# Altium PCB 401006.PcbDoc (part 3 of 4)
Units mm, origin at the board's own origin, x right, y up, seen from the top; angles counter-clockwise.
Board outline 117 x 63.5 mm, 4 copper layers (Top Layer, Mid-Layer 1, Mid-Layer 2, Bottom Layer), stack 1.68 mm thick; 205 components, 151 nets, 838 pads, 1570 vias.
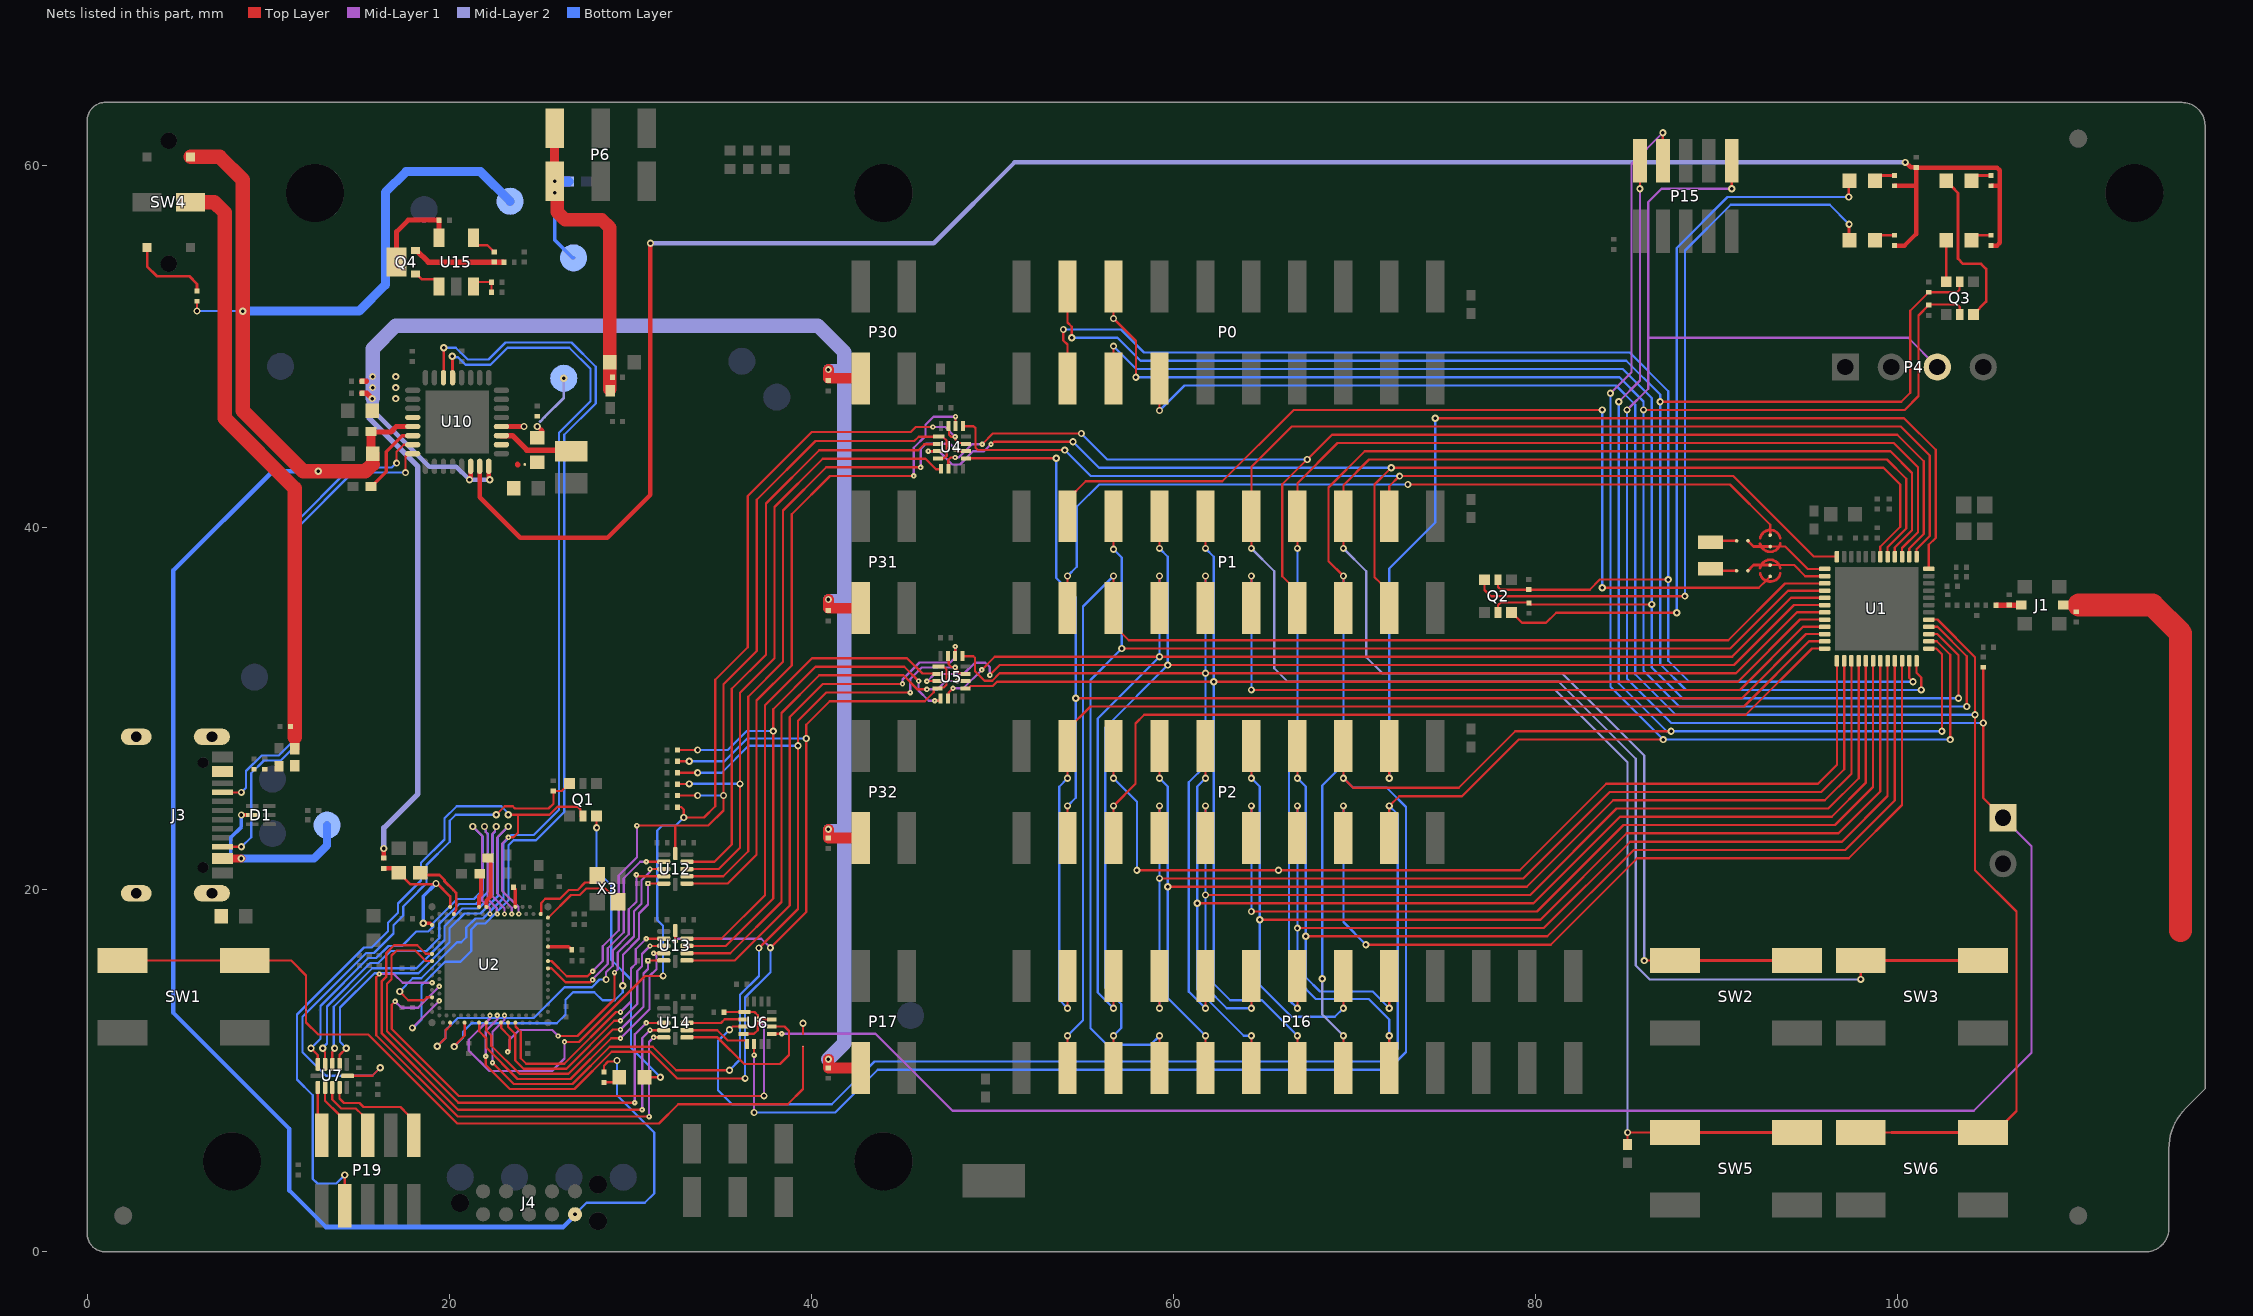
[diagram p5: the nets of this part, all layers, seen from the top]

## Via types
v1: diameter 0.4, hole 0.2, Top Layer to Bottom Layer, tented both sides, 1458 vias
v2: diameter 0.3, hole 0.1, Top Layer to Mid-Layer 1, tented top, 71 vias
v3: diameter 0.5, hole 0.25, Top Layer to Bottom Layer, tented both sides, 24 vias
v4: diameter 0.3, hole 0.1, Top Layer to Mid-Layer 1, tented both sides, 17 vias

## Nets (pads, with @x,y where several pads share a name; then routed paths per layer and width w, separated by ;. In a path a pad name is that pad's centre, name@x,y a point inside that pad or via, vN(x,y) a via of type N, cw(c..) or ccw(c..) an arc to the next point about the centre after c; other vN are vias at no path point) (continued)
NetC39_2: C39.2 U2.A15 | length 2.8
  Top Layer w0.225: U2.A15@22.06,19.064 22.06,19.42 22.286,19.646 22.286,21.619 C39.2@22.151,21.754
NetC42_1: C42.1 R40.1 U2.A5 U2.E1 | length 7.9
  Top Layer w0.15: C42.1@17,21.184 C42.1@17.231,20.952 ; C42.1@17.226,20.947 17.866,20.306 19.231,20.306 v1(19.275,20.35) 19.347,20.35 20.06,19.637 U2.A5@20.06,19.064
  Top Layer w0.2: v1@18.577,18.152 18.966,18.152 19.054,18.064 U2.E1@19.06,18.064
  Top Layer w0.25: R40.1@16.394,21.184 C42.1@17,21.184
  Bottom Layer w0.2: v1(18.575,18.15) 18.575,19.65 v1(19.275,20.35)
NetC43_1: C43.1 U2.B6 | length 3.7
  Top Layer w0.15: C43.1@18.527,20.825 19.472,20.825 19.75,20.547 19.75,20.475 20.235,19.99 20.391,19.834 20.391,18.938 ; U2.B6@20.26,18.664 20.391,18.934
  Top Layer w0.187: C43.1@18.4,20.952 C43.1@18.552,20.8
NetC44_1: C44.1 U2.A23 | length 1.1
  Top Layer w0.2: C44.1@23.55,20.154 23.55,20.139 23.66,20.029 U2.A23@23.66,19.064
NetC45_2: C45.2 U2.A13 | length 1.9
  Top Layer w0.225: U2.A13@21.66,19.064 21.66,19.644 21.77,19.754 C45.2@21.77,20.891
NetC59_1: C59.1 J3.SHLD
NetC64_2: C64.2 R2.2 R3.2 R19.2 R20.2 U10.31 | length 114.9
  Top Layer w0.25: U10.31@21.692,43.396 21.692,41.686 23.928,39.45 28.749,39.45 31.125,41.826 v1(31.125,55.727) ; R3.2@99.848,55.594 100.403,55.594 101.039,56.23 101.039,58.896 ; R19.2@99.848,58.896 101.039,58.896 ; v1(100.445,60.185) 100.468,60.185 100.743,59.91 101.029,59.91 C64.2@101.039,59.9 ; R2.2@105.182,55.594 105.515,55.594 105.661,55.74 105.661,58.896 ; R20.2@105.182,58.896 105.661,58.896 ; 101.039,58.896 C64.2@101.039,59.9 ; C64.2@101.039,59.9 105.515,59.9 105.661,59.754 105.661,58.896
  Mid-Layer 2 w0.25: v1(31.125,55.727) 46.777,55.727 51.235,60.185 v1(100.445,60.185)
NetC72_1: C72.1 R43.2 U15.3 | length 1.7
  Top Layer w0.125: U15.3@21.35,53.325 21.35,53.337 21.587,53.575 C72.1@22.35,53.575 R43.2@22.35,53.025
NetJ3_A5: J3.A5 U10.23 | length 26.4
  Top Layer w0.125: J3.A5@7.485,25.384 v1(8.526,25.384) ; v1(17.1,43.575) 17.097,43.578 17.097,44.197 17.493,44.593 17.988,44.593 U10.23@17.992,44.596
  Bottom Layer w0.125: v1(8.526,25.384) 8.785,25.643 8.785,26.565 9.648,27.428 10.586,27.428 11.275,28.116 11.275,40.046 14.556,43.327 16.839,43.327 17.087,43.575 v1(17.1,43.575)
NetJ3_B5: J3.B5 U10.24 | length 29.1
  Top Layer w0.125: v1(17.594,43.05) 17.591,43.053 17.591,43.935 17.752,44.096 U10.24@17.992,44.096
  Top Layer w0.15: J3.B5@7.485,22.384 v1(8.529,22.384)
  Bottom Layer w0.125: v1(8.529,22.384) 8.538,22.384 9.065,22.911 9.065,26.44 9.775,27.15 10.701,27.15 11.553,28.001 11.553,39.931 14.671,43.05 v1(17.594,43.05)
NetL8_2: L8.2 U10.3 | length 4.2
  Top Layer w0.3: U10.3@22.892,45.096 23.492,45.096 24.292,44.296 L8.2@26.749,44.296
NetLD1_1: LD1.1 Q1.6 | length 16.8
  Top Layer w0.125: v1(28.15,23.425) Q1.6@28.15,24.082 ; LD1.1@30.802,9.652 v1(31.674,9.652)
  Bottom Layer w0.125: v1(28.15,23.425) 28.15,21.075 28.966,20.259 28.966,16.14 30.055,15.051 30.055,11.272 v1(31.674,9.652)
NetLD1_2: LD1.2 R5.1 | length 1.4
  Top Layer w0.125: LD1.2@29.12,9.937 LD1.2@29.405,9.652
  Top Layer w0.15: R5.1@28.56,9.367 29.12,9.367 LD1.2@29.405,9.652
NetLD2_1: LD2.1 Q2.6 | length 41.3
  Top Layer w0.125: Q2.6@78.7,35.331 79.278,34.754 80.601,34.754 81.16,35.312 v1(87.814,35.312)
  Top Layer w0.15: v1(97.316,58.277) 97.316,59.125 LD2.1@97.371,59.181
  Bottom Layer w0.125: v1(87.814,35.312) 87.814,55.463 90.629,58.278 v1(97.316,58.277)
NetLD2_2: LD2.2 R19.1 | length 1.2
  Top Layer w0.15: LD2.2@98.768,59.181 99.053,59.466 R19.1@99.848,59.466
NetLD3_1: LD3.1 Q3.6 | length 9.2
  Top Layer w0.15: LD3.1@102.705,59.155 103.011,58.849 103.358,58.502 103.358,54.87 103.645,54.583 104.636,54.583 104.915,54.304 104.915,52.502 Q3.6@104.205,51.793
NetLD3_2: LD3.2 R20.1 | length 1.2
  Top Layer w0.15: LD3.2@104.102,59.181 104.387,59.466 R20.1@105.182,59.466
NetLD4_1: LD4.1 Q2.3 | length 42.3
  Top Layer w0.125: Q2.3@77.2,37.131 77.2,36.563 77.536,36.227 v1(88.272,36.227)
  Top Layer w0.15: v1(97.341,56.777) 97.341,55.909 LD4.1@97.371,55.879
  Bottom Layer w0.125: v1(88.272,36.227) 88.272,55.322 90.8,57.85 96.268,57.85 v1(97.341,56.777)
NetLD4_2: LD4.2 R3.1 | length 0.8
  Top Layer w0.15: LD4.2@99.053,56.164 R3.1@99.848,56.164
NetLD5_1: LD5.1 Q3.3 | length 2.3
  Top Layer w0.15: Q3.3@102.705,53.593 LD5.1@102.705,55.879
NetLD5_2: LD5.2 R2.1 | length 0.8
  Top Layer w0.15: LD5.2@104.387,56.164 R2.1@105.182,56.164
NetQ1_3: Q1.3 R8.1 U7.12 | length 31.3
  Top Layer w0.125: U7.12@14.4,9.725 15.75,9.725 v1(16.2,10.175) ; v1(22.608,24.15) 23.071,24.612 23.517,24.612 23.641,24.488 25.491,24.488 25.766,24.763 R8.1@25.766,25.449 ; R8.1@25.76,25.455 26.223,25.455 26.477,25.71 Q1.3@26.651,25.71
  Bottom Layer w0.125: v1(16.2,10.175) 15.75,9.725 13.2,9.725 11.9,11.025 11.9,12.983 15.429,16.512 15.848,16.512 16.925,17.589 16.925,18.05 17.462,18.588 17.462,19.081 18.183,19.802 18.371,19.99 18.753,20.372 18.753,21.369 20.043,22.66 20.043,23.824 20.369,24.15 v1(22.608,24.15)
NetQ4_1: Q4.1 U15.1 | length 1.7
  Top Layer w0.15: Q4.1@18.15,54.025 18.2,54.025 18.5,53.725 19.225,53.725 19.45,53.5 U15.1@19.45,53.325
NetQ4_2: Q4.2 R9.1 R38.2 | length 5.1
  Top Layer w0.3: Q4.2@18.15,55.325 18.2,55.325 18.851,54.674 R9.1@23.006,54.674
NetR7_1: R7.1 U2.L31 | length 1.4
  Top Layer w0.187: U2.L31@25.46,16.864 26.597,16.864 26.719,16.743 26.734,16.743 26.775,16.702 R7.1@26.775,16.687
NetR21_2: R21.2 U4.5 U12.9 | length 37
  Top Layer w0.125: R21.2@32.61,25.842 v1@33.255,25.842 ; U12.9@33.14,21.15 34.903,21.15 36.075,22.321 36.075,30.889 37.978,32.792 37.978,41.147 40.646,43.815 46.322,43.815 46.903,43.233 47.13,43.233 47.16,43.262 U4.5@47.178,43.262
  Bottom Layer w0.125: v1(33.267,25.855) v1(36.075,25.855)
NetR22_2: R22.2 U5.5 U13.9 | length 33.4
  Top Layer w0.125: R22.2@32.61,27.726 v1(33.728,27.726) ; U13.9@33.14,16.9 35.284,16.9 37.903,19.519 37.903,29.982 40.246,32.325 45.147,32.325 v2(45.936,31.536) ; v2(46.825,30.45) 47.113,30.45 47.16,30.497 U5.5@47.16,30.561
  Mid-Layer 1 w0.125: v2(45.936,31.536) 45.936,31.014 46.5,30.45 v2(46.825,30.45)
  Bottom Layer w0.125: v1(33.728,27.726) 35.401,27.726 36.445,28.77 v1(37.903,28.77)
NetR36_1: R36.1 SW4.3 | length 4.6
  Top Layer w0.15: SW4.3@3.321,55.488 3.321,54.428 3.849,53.9 5.646,53.9 6.075,53.471 R36.1@6.075,53.085
NetR38_1: R38.1 U15.4 | length 1.6
  Top Layer w0.125: U15.4@21.35,56.025 21.35,55.825 21.572,55.603 22.126,55.603 R38.1@22.485,55.245
NetSB1_2: SB1.2 SB2.1 SW1.2 | length 45.9
  Top Layer w0.125: SW1.2@1.963,16.097 SW1.2@8.713,16.097 11.277,16.097 12.1,15.273 12.1,14.91 ; 12.1,14.864 SB2.1@12.1,13.364 12.1,12.675 12.766,12.009 15.541,12.009 20.457,7.093 31.594,7.093 32.661,8.16 38.716,8.16 39.55,8.994 SB1.2@39.55,11.35
NetSB3_2: SB3.2 X2.1 | length 1.5
  Top Layer w0.15: X2.1@89.689,39.192 89.777,39.28 SB3.2@91.129,39.28
NetSB4_2: SB4.2 X2.2 | length 1.5
  Top Layer w0.15: X2.2@89.689,37.742 89.802,37.629 SB4.2@91.129,37.629
NetU2_B30: U2.B30 X3.3 | length 4.3
  Top Layer w0.125: U2.B30@25.06,18.664 25.079,18.684 25.079,18.754 25.085,18.76 25.085,19.273 25.315,19.502 26.122,19.502 26.61,19.99 27.102,19.99 27.515,20.403 27.79,20.403 X3.3@28.181,20.794
NetU2_C31: U2.C31 X3.1 | length 4.9
  Top Layer w0.125: U2.C31@25.46,18.464 25.485,18.464 26.735,19.715 27.216,19.715 27.573,20.072 28.632,20.072 28.948,19.756 28.968,19.756 29.331,19.394 X3.1@29.331,19.344
NetU4_2: U4.2 U12.10 | length 33.4
  Top Layer w0.125: U12.10@33.14,21.55 34.657,21.55 35.617,22.511 35.617,31.103 37.503,32.989 37.503,41.344 40.45,44.29 45.926,44.29 46.255,44.619 46.984,44.619 U4.2@47.003,44.637
NetU4_10: U4.10 U12.8 | length 36
  Top Layer w0.125: U12.8@33.14,20.75 35.15,20.75 36.532,22.132 36.532,30.674 38.453,32.596 38.453,40.95 40.843,43.34 v2@46.05,43.34
  Top Layer w0.127: v2(47.946,44.371) 47.966,44.371 48.1,44.237 U4.10@48.553,44.237
  Mid-Layer 1 w0.125: v2(46.05,43.336) 46.05,44.35 46.341,44.641 47.675,44.641 v2(47.946,44.371)
NetU4_14: U4.14 U12.7 | length 37.2
  Top Layer w0.125: U12.7@33.14,20.35 35.396,20.35 36.989,21.943 36.989,30.459 38.928,32.399 38.928,40.753 41.04,42.865 v2(45.675,42.865) ; U4.14@47.971,45.619 U4.14@47.978,45.612
  Top Layer w0.127: U4.14@47.978,45.612 v2(47.977,46.144)
  Mid-Layer 1 w0.125: v2(45.675,42.865) 45.675,44.425 46.325,45.075 46.325,45.7 46.769,46.144
  Mid-Layer 1 w0.127: 46.769,46.144 v2(47.977,46.144)
NetU5_2: U5.2 U13.10 | length 26.8
  Top Layer w0.125: U13.10@33.148,17.308 U13.10@33.14,17.3 35.037,17.3 37.446,19.709 37.446,30.197 40.049,32.8 45.3,32.8 46.152,31.948 46.863,31.948 46.875,31.936 U5.2@46.985,31.936
NetU5_10: U5.10 U13.8 | length 28.4
  Top Layer w0.125: U13.8@33.14,16.5 35.531,16.5 38.361,19.33 38.361,29.768 40.443,31.85 45.1,31.85 45.875,31.075 v2(46.4,31.075)
  Top Layer w0.127: v2(48.07,31.536) U5.10@48.535,31.536
  Mid-Layer 1 w0.125: v2(46.4,31.075) 46.975,31.075 47.436,31.536 v2(48.07,31.536)
NetU5_14: U5.14 U13.7 | length 29.1
  Top Layer w0.125: U13.7@33.14,16.1 35.777,16.1 38.818,19.141 38.818,29.553 40.64,31.375 v2(45.05,31.375) ; U5.14@47.953,32.918 U5.14@47.96,32.911
  Top Layer w0.127: U5.14@47.96,32.911 v2@47.96,33.442
  Mid-Layer 1 w0.125: v2(45.05,31.375) 45.05,31.625 45.989,32.564 47.274,32.564 47.275,32.565
  Mid-Layer 1 w0.127: 47.275,32.565 47.69,32.565 47.96,32.835 v2(47.96,33.442)
NetU6_2: U6.2 U14.9 | length 3.2
  Top Layer w0.125: U14.9@33.14,12.65 35.028,12.65 35.228,12.85 U6.2@36.275,12.85
NetU6_5: U6.5 U14.8 | length 3.7
  Top Layer w0.125: U14.8@33.14,12.25 34.814,12.25 35.389,11.675 36.402,11.675 36.45,11.627 U6.5@36.45,11.475
NetU6_10: U6.10 U14.7 | length 8.8
  Top Layer w0.127: U14.7@33.14,11.85 34.831,11.85 36.306,10.375 38.277,10.375 38.775,10.873 38.775,12.2 38.525,12.45 U6.10@37.825,12.45
NRESET: P3.1 P4.3 P15.10 R1.2 SB1.1 U6.9 | length 166.9
  Top Layer w0.125: U6.9@37.825,12.05 37.826,12.051 v2(38.377,12.051) ; SB1.1@39.55,12.05 v1(39.55,12.634) ; v1(90.864,58.731) P15.10@90.864,60.28 ; R1.2@104.756,32.296 v1(104.756,29.216) 104.756,25.072 P3.1@105.845,23.983
  Mid-Layer 1 w0.125: v2(38.377,12.051) 39.55,12.051 ; v1(39.55,12.634) 39.55,12.051 ; v1(85.071,46.514) 86.24,47.682 86.24,50.494 ; v1(90.864,58.731) 86.976,58.731 86.24,57.995 86.24,50.494 ; P4.3@102.214,48.884 100.604,50.494 86.24,50.494 ; P3.1@105.845,23.983 107.423,22.405 107.423,11.005 104.223,7.804 47.809,7.804 43.562,12.051 39.55,12.051
  Bottom Layer w0.125: v1(85.071,46.514) 85.071,31.666 87.521,29.216 v1(104.756,29.216)
P0.00: P0.3 Q2.2 R10.1 U1.23 | length 77.8
  Top Layer w0.125: v1(53.936,50.959) 53.936,50.349 54.164,50.121 P0.3@54.164,48.26 ; Q2.2@77.95,37.131 77.95,36.731 78.096,36.586 R10.1@79.652,36.586 83.017,36.586 83.573,37.141 v1(87.357,37.141) ; U1.23@100.668,32.65 100.668,31.704 v1(100.87,31.502)
  Bottom Layer w0.125: v1@53.936,50.957 57.116,50.957 58.384,49.689 85.219,49.689 87.357,47.551 87.357,32.657 88.512,31.502 v1(100.87,31.502)
P0.01: P0.4 Q3.2 R11.1 U1.24 | length 90.5
  Top Layer w0.125: v1(86.9,46.971) 100.223,46.971 100.718,47.465 100.718,51.985 R11.1@101.743,53.011 103.299,53.011 103.441,53.153 Q3.2@103.441,53.578 ; U1.24@101.068,32.65 101.068,31.99 101.327,31.731 v1(101.327,31.045)
  Top Layer w0.127: P0.4@54.164,53.34 54.164,51.34 54.394,51.11 v1(54.394,50.502)
  Bottom Layer w0.125: v1(54.394,50.502) 56.928,50.502 58.196,49.234 85.031,49.234 86.902,47.362 86.902,32.468 88.325,31.045 v1(101.327,31.045)
P0.02: P0.5 Q2.5 R12.1 U1.27 | length 78.7
  Top Layer w0.125: P0.5@56.704,48.26 v1(56.704,50.038) ; Q2.5@77.95,35.331 77.95,35.731 78.096,35.877 R12.1@79.658,35.877 ; R12.1@79.661,35.871 79.763,35.77 v1(86.443,35.77) ; U1.27@101.748,34.13 102.211,34.13 103.385,32.957 v1(103.385,30.588)
  Bottom Layer w0.125: v1(56.704,50.038) 57.967,48.774 84.84,48.774 86.443,47.172 v1(86.443,35.77) 86.443,32.284 88.139,30.588 v1(103.385,30.588)
P0.03: P0.6 Q3.5 R27.1 U1.28 | length 96.2
  Top Layer w0.125: P0.6@56.704,53.34 v1(56.704,51.562) 57.944,50.322 v1(57.944,48.317) ; v1(85.986,46.514) 100.413,46.514 101.175,47.276 101.175,51.734 R27.1@101.743,52.303 ; U1.28@101.748,34.53 102.219,34.53 103.842,32.907 v1(103.842,30.131) ; R27.1@101.754,52.338 103.31,52.338 103.455,52.193 Q3.5@103.455,51.793
  Bottom Layer w0.125: v1(57.944,48.317) 84.651,48.317 85.986,46.983 v1(85.986,46.514) 85.986,32.098 87.953,30.131 v1(103.842,30.131)
P0.04: P0.7 SW6.2 U1.29 | length 102.2
  Top Layer w0.125: v1(59.244,46.482) P0.7@59.244,48.26 ; SW6.2@97.982,6.594 99.684,6.594 ; U1.29@101.748,34.93 102.225,34.93 104.299,32.857 v1(104.299,29.674) 104.299,21.088 106.585,18.802 106.585,7.779 105.401,6.594 SW6.2@104.732,6.594
  Top Layer w0.15: 99.684,6.594 SW6.2@104.732,6.594
  Bottom Layer w0.125: v1(59.244,46.482) 60.622,47.86 84.462,47.86 85.528,46.793 85.528,31.912 87.767,29.674 v1(104.299,29.674)
P1.00: P1.3 SB5.2 | length 46.1
  Top Layer w0.125: P1.3@54.164,35.56 v1(54.164,37.338) ; v1@72.967,42.399 90.761,42.399 92.983,40.176 92.983,39.88 SB5.2@92.983,39.592
  Bottom Layer w0.125: v1(54.164,37.338) 54.672,37.846 54.672,41.159 55.912,42.399 v1@72.967,42.399
  other v1: 72.967,42.395
P1.00/XL1: SB3.1 SB5.1 U1.1 | length 4.9
  Top Layer w0.125: SB5.1@92.983,38.967 93.482,38.967 93.816,38.967 95.053,37.73 U1.1@95.988,37.73
  Top Layer w0.15: SB3.1@91.754,39.28 92.067,38.967 92.485,38.967 SB5.1@92.983,38.967
P1.01: P1.4 SB6.2 | length 51.9
  Top Layer w0.125: P1.4@54.164,40.64 54.164,41.567 55.174,42.577 62.719,42.577 66.656,46.514 v1(83.7,46.514) ; v1(83.7,36.684) 92.351,36.684 92.747,37.08 SB6.2@92.983,37.316
  Bottom Layer w0.125: v1(83.7,36.684) v1(83.7,46.514)
P1.01/XL2: SB4.1 SB6.1 U1.2 | length 4.6
  Top Layer w0.125: SB6.1@92.983,37.941 93.482,37.941 94.309,37.941 94.92,37.33 U1.2@95.988,37.33
  Top Layer w0.15: SB4.1@91.754,37.629 92.067,37.941 92.485,37.941 SB6.1@92.983,37.941
P1.02: P1.5 P16.3 U1.3 | length 71.9
  Top Layer w0.125: P16.3@54.164,10.16 v1(54.164,11.938) ; v1(56.704,37.338) P1.5@56.704,35.56 56.704,34.633 57.549,33.788 90.662,33.788 93.804,36.93 U1.3@95.988,36.93
  Bottom Layer w0.125: v1(54.164,11.938) 55.023,12.797 55.023,35.657 v1(56.704,37.338)
P1.03: P1.6 P16.7 U1.4 | length 75.5
  Top Layer w0.125: v1(56.704,38.822) P1.6@56.704,40.6 ; v1(57.161,33.331) 90.771,33.331 93.97,36.53 U1.4@95.988,36.53 ; P16.7@59.244,10.16 v1(59.244,11.938)
  Bottom Layer w0.125: v1(56.704,38.822) 57.161,38.365 v1(57.161,33.331) 55.429,31.599 55.429,12.351 56.34,11.44 58.751,11.44 v1@59.244,11.933
P1.04/AIN0: P1.7 P16.6 U1.5 U5.6 | length 80.1
  Top Layer w0.125: U5.6@47.56,30.561 47.608,30.609 47.608,30.905 v2(47.839,31.136) ; v2(49.425,32.15) 50.149,32.874 v1(59.244,32.874) 90.879,32.874 94.135,36.13 U1.5@95.988,36.13 ; v1(56.704,13.462) P16.6@56.704,15.24 ; P1.7@59.244,35.56 v1(59.244,37.338)
  Mid-Layer 1 w0.125: v2(47.839,31.136) 48.411,31.136 v2(49.425,32.15)
  Bottom Layer w0.125: v1(56.704,13.462) 55.836,14.331 55.836,29.465 v1(59.244,32.874) v1(59.244,37.338)
P1.05/AIN1: P1.8 P16.5 U1.6 U5.3 | length 85.4
  Top Layer w0.125: v2(49.875,31.866) 50.426,32.417 v1(59.701,32.417) 90.988,32.417 94.301,35.73 U1.6@95.988,35.73 ; P16.5@56.704,10.16 v1(56.704,11.938) ; v1(59.244,38.862) P1.8@59.244,40.64
  Top Layer w0.127: v2(46.4,31.525) 46.411,31.536 U5.3@46.985,31.536
  Mid-Layer 1 w0.127: v2(46.4,31.525) 46.411,31.525 46.811,31.925 48.425,31.925 49.05,32.55 49.625,32.55 49.875,32.3 v2(49.875,31.866)
  Bottom Layer w0.125: v1(56.704,11.938) 57.131,12.365 57.131,13.697 56.242,14.586 56.242,28.957 v1(59.701,32.417) 59.701,38.405 v1(59.244,38.862)
P1.06/AIN2: P1.9 P16.10 U1.7 U5.13 | length 78.4
  Top Layer w0.125: U5.13@48.36,32.911 48.954,32.911 49.05,32.815 49.05,32.083 49.58,31.553 50.004,31.553 50.411,31.96 v1(61.784,31.96) 91.096,31.96 94.467,35.33 U1.7@95.988,35.33 ; v1(61.784,13.462) P16.10@61.784,15.24 ; P1.9@61.784,35.56 v1(61.784,37.338)
  Bottom Layer w0.125: v1(61.784,13.462) 60.868,14.378 60.868,25.94 61.784,26.856 v1(61.784,31.96) v1(61.784,37.338)
P1.07/AIN3: P1.10 P16.13 U1.8 U5.9 | length 82.6
  Top Layer w0.125: U5.9@48.535,31.136 48.7,31.136 48.748,31.184 48.748,31.191 48.821,31.264 50.033,31.264 50.272,31.502 v1(62.243,31.502) 91.205,31.502 94.632,34.93 U1.8@95.988,34.93 ; v1(61.784,38.862) P1.10@61.784,40.64 ; P16.13@66.864,10.16 v1(66.864,11.938)
  Bottom Layer w0.125: v1(61.784,38.862) 62.243,38.404 v1(62.243,31.502) 62.243,14.811 63.154,13.9 64.902,13.9 v1(66.864,11.938)
P1.08: C41.2 P1.11 SW5.2 U1.9 | length 94.1
  Top Layer w0.125: v1(64.324,31.045) 91.313,31.045 94.798,34.53 U1.9@95.988,34.53 ; P1.11@64.324,35.56 v1(64.324,37.338) ; C41.2@85.105,5.926 v1(85.105,6.594) SW5.2@87.721,6.594
  Top Layer w0.15: SW5.2@87.721,6.594 SW5.2@94.471,6.594
  Mid-Layer 2 w0.125: v1(64.324,31.045) 81.109,31.045 85.105,27.049 v1(85.105,6.594)
  Bottom Layer w0.125: v1(64.324,31.045) v1(64.324,37.338)
P1.09: P1.12 SW3.2 U1.37 | length 110.6
  Top Layer w0.125: v1(64.324,38.862) P1.12@64.324,40.64 64.324,43.378 66.546,45.599 100.191,45.599 101.796,43.994 101.796,39.544 101.068,38.816 U1.37@101.068,38.41
  Top Layer w0.152: v1(97.982,15.053) SW3.2@97.982,16.094 SW3.2@104.732,16.094
  Mid-Layer 2 w0.125: v1(64.324,38.862) 65.589,37.597 65.589,32.239 66.326,31.502 81.298,31.502 85.562,27.239 85.562,15.822 86.332,15.053 v1(97.982,15.053)
P1.10: P1.13 U1.38 U4.6 | length 70.8
  Top Layer w0.125: U4.6@47.578,43.262 47.578,43.749 47.714,43.885 v2(47.953,43.885) ; v2(49.45,44.619) 50.041,45.209 v1(54.93,45.209) ; P1.13@66.889,36.195 66.419,36.666 66.419,36.933 66.032,37.319 66.032,42.403 68.771,45.142 100.002,45.142 101.471,43.673 101.471,39.658 100.668,38.855 U1.38@100.668,38.41
  Mid-Layer 1 w0.127: v2(47.953,43.885) 48.16,43.885 48.894,44.619 v2(49.45,44.619)
  Bottom Layer w0.125: v1(54.93,45.209) 56.364,43.775 v1(67.402,43.777)
P1.11: P1.14 P16.14 U1.39 | length 72.2
  Top Layer w0.125: v1(66.864,13.462) P16.14@66.864,15.24 ; v1(66.864,38.862) P1.14@66.864,40.64 66.864,42.464 69.085,44.685 99.812,44.685 101.146,43.351 101.146,39.76 100.268,38.882 U1.39@100.268,38.41
  Bottom Layer w0.125: v1(66.864,13.462) 66.405,13.921 66.405,26.524 66.864,26.983 v1(66.864,38.862)
P1.12: P1.15 P16.15 U1.40 | length 73.7
  Top Layer w0.125: P16.15@69.404,10.16 v1(69.404,11.938) ; P1.15@69.404,35.56 v1(69.404,37.338) 68.582,38.16 68.582,42.223 70.587,44.228 99.623,44.228 100.821,43.03 100.821,39.861 99.868,38.908 U1.40@99.868,38.41
  Mid-Layer 2 w0.125: v1(68.234,15.094) 68.234,13.108 v1(69.404,11.938)
  Bottom Layer w0.125: v1(68.234,15.094) 68.234,25.762 69.404,26.932 v1(69.404,37.338)
P1.13: P1.16 SW2.2 U1.41 | length 84.3
  Top Layer w0.125: v1(69.404,38.862) P1.16@69.404,40.64 69.404,42.354 70.821,43.771 99.434,43.771 100.496,42.708 100.496,39.96 99.468,38.933 U1.41@99.468,38.41 ; v1(86.019,16.094) SW2.2@87.721,16.094
  Top Layer w0.15: SW2.2@87.721,16.094 SW2.2@94.471,16.094
  Mid-Layer 2 w0.125: v1(69.404,38.862) 70.669,37.597 70.669,32.849 71.558,31.96 81.487,31.96 86.019,27.428 v1(86.019,16.094)
P1.14: P1.17 U1.42 U4.3 | length 68.7
  Top Layer w0.125: v2(49.939,44.619) 49.967,44.619 50.099,44.752 v1(54.469,44.752) ; P1.17@71.969,35.877 71.969,36.462 71.499,36.933 71.467,36.933 71.125,37.275 71.125,42.39 v1(72.053,43.318) ; v1@72.053,43.313 99.244,43.313 100.166,42.392 100.166,40.055 99.068,38.957 U1.42@99.068,38.41
  Top Layer w0.127: v2(46.472,44.237) U4.3@47.003,44.237
  Mid-Layer 1 w0.127: v2(46.472,44.237) 47.063,44.237 47.8,43.5 48.225,43.5 48.95,44.225 49.545,44.225 v2(49.939,44.619)
  Bottom Layer w0.125: v1(54.469,44.752) 55.903,43.318 v1(72.053,43.318)
P1.15: P1.18 U1.48 U4.13 | length 54.4
  Top Layer w0.125: U4.13@48.378,45.612 48.971,45.612 49.075,45.509 49.075,44.425 49.205,44.295 v1(54.007,44.295) ; P1.18@71.944,40.64 71.944,42.29 v1(72.51,42.856) 90.939,42.856 95.384,38.41 U1.48@96.668,38.41
  Bottom Layer w0.125: v1(54.007,44.295) 55.445,42.856 v1(72.51,42.856)
P1.16: P2.3 U1.10 U4.9 | length 69.4
  Top Layer w0.125: U4.9@48.553,43.837 v1(53.545,43.837) ; P2.3@54.164,22.86 v1(54.164,24.638) ; v1(54.62,30.588) 91.422,30.588 94.964,34.13 U1.10@95.988,34.13
  Bottom Layer w0.125: v1(53.545,43.837) 53.545,37.233 54.62,36.159 v1(54.62,30.588) 54.62,25.093 v1(54.164,24.638)
P1.17: P2.4 P16.4 U1.11 | length 61.4
  Top Layer w0.125: v1(54.164,13.462) P16.4@54.164,15.24 ; v1(54.164,26.162) P2.4@54.164,27.94 54.164,28.867 55.428,30.131 91.53,30.131 95.13,33.73 U1.11@95.988,33.73
  Bottom Layer w0.125: v1(54.164,13.462) 53.702,13.924 53.702,25.7 v1(54.164,26.162)
P1.18: P2.5 U1.12 | length 46.6
  Top Layer w0.125: P2.5@56.704,22.86 v1(56.704,24.638) 57.922,25.855 57.922,29.191 58.404,29.674 91.639,29.674 95.295,33.33 U1.12@95.988,33.33
P1.19: P2.6 U1.13 | length 54.2
  Top Layer w0.125: v1(56.704,26.162) P2.6@56.704,27.94 ; v1(57.998,21.088) 79.153,21.088 83.929,25.864 95.62,25.864 96.668,26.912 U1.13@96.668,32.65
  Bottom Layer w0.125: v1(56.704,26.162) 57.998,24.868 v1(57.998,21.088)
  other v1: 65.817,21.088
P1.20: P2.7 P16.8 U1.14 | length 62.2
  Top Layer w0.125: v1(59.244,13.462) P16.8@59.244,15.24 ; v1(59.244,20.631) 79.343,20.631 84.118,25.406 95.809,25.406 97.068,26.665 U1.14@97.068,32.65 ; v1(59.244,24.638) P2.7@59.244,22.86 59.248,22.856 P2.7@59.248,21.7
  Bottom Layer w0.125: v1(59.244,13.462) v1(59.244,20.631) v1(59.244,24.638)
P1.21: P2.8 P16.9 U1.15 | length 65.4
  Top Layer w0.125: v1(59.244,26.162) P2.8@59.244,27.94 ; v1(59.7,20.174) 79.532,20.174 84.307,24.949 95.999,24.949 97.468,26.419 U1.15@97.468,32.65 ; P16.9@61.784,10.16 v1(61.784,11.938)
  Bottom Layer w0.125: v1(59.244,26.162) 59.7,25.707 v1(59.7,20.174) 59.7,14.023 v1(61.784,11.938)
P1.22: P2.9 P16.12 U1.16 | length 61.8
  Top Layer w0.125: v1(61.784,19.717) 79.722,19.717 84.497,24.492 96.188,24.492 97.868,26.172 U1.16@97.868,32.65 ; P2.9@61.784,22.86 v1(61.784,24.638) ; v1(64.324,13.462) P16.12@64.324,15.24
  Bottom Layer w0.125: v1(61.784,24.638) v1(61.784,19.717) 61.784,14.635 62.957,13.462 v1(64.324,13.462)
P1.23: P2.10 P16.11 U1.17 | length 65.9
  Top Layer w0.125: v1@61.327,19.26 79.911,19.26 84.686,24.035 96.377,24.035 98.268,25.926 U1.17@98.268,32.65 ; v1(61.784,26.162) P2.10@61.784,27.94 ; P16.11@64.324,10.16 v1(64.324,11.938)
  Bottom Layer w0.125: v1(61.784,26.162) 61.327,25.705 v1(61.327,19.261) 61.327,14.508 63.897,11.938 v1(64.324,11.938)
P1.24: P2.11 U1.18 | length 51.8
  Top Layer w0.125: v1(64.324,18.802) 80.1,18.802 84.876,23.578 96.567,23.578 98.668,25.679 U1.18@98.668,32.65 ; P2.11@64.324,22.86 v1(64.324,24.638)
  Bottom Layer w0.125: v1(64.324,18.802) v1(64.324,24.638)
P1.25: P2.12 P16.16 U1.19 | length 65.2
  Top Layer w0.125: v1(64.324,26.162) P2.12@64.324,27.94 ; v1(64.78,18.345) 80.29,18.345 85.065,23.12 96.756,23.12 99.068,25.433 U1.19@99.068,32.65 ; v1(69.404,13.462) P16.16@69.404,15.24
  Bottom Layer w0.125: v1(64.324,26.162) 64.78,25.707 v1(64.78,18.345) 64.78,14.738 66.532,12.986 68.928,12.986 v1(69.404,13.462)
P1.26: P2.13 P16.17 U1.20 | length 63.2
  Top Layer w0.125: v1(66.864,17.888) 80.479,17.888 85.254,22.663 96.946,22.663 99.468,25.186 U1.20@99.468,32.65 ; P2.13@66.864,22.86 v1(66.864,24.638) ; P16.17@71.944,10.16 v1(71.944,11.938)
  Bottom Layer w0.125: v1(66.864,17.888) 66.864,14.991 67.878,13.976 70.799,13.976 71.944,12.832 v1(71.944,11.938) ; v1@66.864,17.89 v1(66.864,24.638)
P1.27: P2.14 P16.18 U1.21 | length 63.4
  Top Layer w0.125: v1(66.864,26.162) P2.14@66.864,27.94 ; v1(67.32,17.431) 80.668,17.431 85.444,22.206 97.135,22.206 99.868,24.939 U1.21@99.868,32.65 ; v1(71.944,13.462) P16.18@71.944,15.24
  Bottom Layer w0.125: v1(66.864,26.162) 67.32,25.707 v1(67.32,17.431) 67.32,15.17 68.107,14.383 71.023,14.383 v1(71.944,13.462)
P1.28: P2.15 U1.22 | length 50.7
  Top Layer w0.125: P2.15@69.404,22.86 v1(69.404,24.638) ; v1(70.649,16.974) 80.858,16.974 85.633,21.749 97.324,21.749 100.268,24.693 U1.22@100.268,32.65
  Bottom Layer w0.125: v1(69.404,24.638) 69.404,18.218 v1(70.649,16.974)
P1.29/SWDIO: P2.16 P15.2 U1.25 U6.6 | length 133.6
  Top Layer w0.125: v2(36.85,10.873) U6.6@36.85,11.475 ; P2.16@69.404,27.94 v1(69.404,26.162) 69.931,25.635 75.773,25.635 78.897,28.759 v1(87.51,28.759) ; v1(85.784,58.731) P15.2@85.784,60.28 ; U1.25@101.748,33.33 102.156,33.33 102.47,33.016 v1(102.47,28.759)
  Mid-Layer 1 w0.125: v1(36.85,7.703) v2(36.85,10.873) ; v1(84.614,46.971) 85.784,48.141 v1(85.784,58.731)
  Bottom Layer w0.125: v1(36.85,7.703) 41.33,7.703 43.686,10.058 71.88,10.058 72.859,11.037 72.859,24.575 71.799,25.635 69.931,25.635 v1(69.404,26.162) ; v1(84.614,46.971) 84.614,31.412 87.267,28.759 v1(87.51,28.759) v1(102.47,28.759)
P1.30/SWDCLK: P2.17 P15.4 U1.26 U6.3 | length 135.1
  Top Layer w0.125: v1(35.49,12.275) 35.666,12.45 U6.3@36.275,12.45 ; P2.17@71.944,22.86 v1(71.944,24.638) 72.484,25.178 75.962,25.178 79.086,28.302 v1(87.078,28.302) ; P15.4@87.054,60.28 v1(87.054,61.829) ; U1.26@101.748,33.73 102.181,33.73 102.927,32.983 v1(102.927,28.302)
  Mid-Layer 1 w0.125: v1(84.157,47.428) 85.324,48.595 85.324,60.099 v1(87.054,61.829)
  Bottom Layer w0.125: v1(35.49,12.275) 34.86,11.645 34.86,8.932 35.632,8.16 41.141,8.16 43.496,10.516 71.69,10.516 72.401,11.227 72.401,24.181 v1(71.944,24.638) ; v1(84.157,47.428) 84.157,31.223 v1(87.078,28.302) v1(102.927,28.302)
P1.31: P2.18 U1.36 | length 57.8
  Top Layer w0.125: v1(71.944,26.162) P2.18@71.944,27.94 ; v1(74.484,46.057) 100.381,46.057 102.122,44.315 102.122,39.442 101.748,39.068 U1.36@101.748,37.73
  Bottom Layer w0.125: v1(71.944,26.162) 71.944,37.756 74.484,40.296 v1(74.484,46.057)
P5V0: C24.2 C26.2 C52.2 C55.2 C56.2 C62.2 C69.1 C70.2 C83.2 P17.1 P30.1 P31.1 P32.1 Q4.3 R4.2 R40.2 TP10.1 U10.4 U10.20 U10.30 U10.32 U15.5 | length 129.3
  Top Layer w0.25: R40.2@16.394,21.754 v1(16.394,22.288) ; v1(21.125,42.65) 21.125,42.718 21.184,42.777 21.184,43.388 U10.30@21.192,43.396 ; U10.32@22.192,43.396 22.195,43.392 22.195,42.772 22.25,42.718 v1(22.25,42.65) ; v1(24.867,45.596) 24.907,45.596 25.138,45.365
  Top Layer w0.27: Q4.3@17.1,54.675 17.1,56.363 17.737,57 C69.1@19.45,57 U15.5@19.45,56.025
  Top Layer w0.3: C70.2@15.185,47.425 15.467,47.425 15.755,47.137 v1(15.757,47.137) ; R4.2@15.185,48.091 15.43,48.091 ; U10.4@22.892,45.596 v1@24.038,45.596
  Top Layer w0.6: v1(40.956,10.643) C83.2@40.956,10.16 P17.1@42.734,10.16 ; v1(40.956,23.343) C52.2@40.956,22.86 P32.1@42.734,22.86 ; v1(40.956,36.043) 40.956,35.56 P31.1@42.734,35.56 ; v1(40.956,48.743) 40.956,48.26 P30.1@42.734,48.26
  Mid-Layer 2 w0.15: 25.025,45.875 25.04,45.875 25.278,46.113 26.334,47.169 v1(26.334,48.26)
  Mid-Layer 2 w0.25: v1(15.757,47.137) 15.763,47.137 16,46.9 16,46.275 18.9,43.375 20.4,43.375 v1(21.125,42.65) v1(22.25,42.65)
  Mid-Layer 2 w0.3: v1(15.757,47.137) 15.757,47.083 15.6,46.926 15.6,46.05 18.275,43.375 18.275,25.306 16.394,23.425 v1(16.394,22.288)
  Mid-Layer 2 w0.6: v1(40.956,23.343) 41.819,23.343 ; v1(40.956,36.043) 41.819,36.043 ; v1(40.956,48.743) 41.819,48.743 41.84,48.764
  Mid-Layer 2 w0.8: v1@15.775,47.155 v1(15.775,47.746) v1(15.775,48.355) 15.775,49.9 17.05,51.175 40.375,51.175 41.84,49.71 41.84,48.772 41.84,11.527 v1(40.956,10.643)
  other v1: 24.142,45.596 17.055,47.137 17.056,47.746 17.056,48.355
PCBANT: C38.2 J1.3 | length 22.7
  Top Layer w1.27: 110.033,35.73 114.1,35.73 115.66,34.171 115.66,17.748
PVSS1: C24.1 C27.1 NT2.2 U10.2 | length 0
  Top Layer w0.3: 23.78,43.496 23.78,43.508 23.792,43.496
RF: C11.2 J1.1 L3.2 | length 1.4
  Top Layer w0.3: L3.2@105.487,35.73 106.235,35.73 J1.1@106.845,35.73
SWD0_CLK: U2.B18 U7.4 | length 24.1
  Top Layer w0.125: v1(13.025,11.25) 13.025,11.149 13.15,11.024 U7.4@13.15,10.365
  Mid-Layer 1 w0.125: v1(21.958,23.5) 22.019,23.439 22.019,23.192 22.116,23.095 22.116,19.51 22.627,18.999 22.627,18.698 v2(22.66,18.664)
  Bottom Layer w0.125: v1(13.025,11.25) 13.025,11.286 13.25,11.511 13.25,13.553 15.652,15.955 16.091,15.955 16.761,16.625 18.75,16.625 19.45,17.325 19.45,18.114 20.561,19.225 21.487,19.225 22.153,19.891 22.153,23.089 22.03,23.212 22.03,23.428 v1(21.958,23.5)
SWD0_CLK_EXT: P19.4 U7.8 | length 3.1
  Top Layer w0.125: U7.8@13.15,9.085 13.15,8.354 13.917,7.587 13.917,6.767 P19.4@14.234,6.45
SWD0_IO: U2.B16 U7.5 | length 24.3
  Top Layer w0.125: v1(12.375,11.25) 12.375,11.246 12.75,10.871 U7.5@12.75,10.365
  Mid-Layer 1 w0.125: v1(21.308,23.5) 21.308,23.496 21.833,22.971 21.833,19.404 22.26,18.977 v2(22.26,18.664)
  Bottom Layer w0.125: v1(12.375,11.25) 12.375,11.254 12.893,11.772 12.893,13.585 15.538,16.23 15.977,16.23 16.647,16.9 17.397,16.9 18.19,17.694 18.849,17.694 19.137,17.982 19.137,18.19 20.447,19.5 21.373,19.5 21.878,20.005 21.878,22.93 21.771,23.037 21.767,23.037 21.308,23.496 v1(21.308,23.5)
SWD0_IO_EXT: P19.2 U7.7 | length 2.7
  Top Layer w0.125: U7.7@12.75,9.085 12.75,6.664 P19.2@12.964,6.45 P19.2@12.975,6.461
SWD0_RESET: U2.B22 U7.2 | length 24.7
  Top Layer w0.125: U7.2@13.95,10.365 13.95,10.871 14.325,11.246 v1(14.325,11.25)
  Mid-Layer 1 w0.125: v1(23.275,23.5) 22.666,22.891 22.666,19.811 23.46,19.017 v2(23.46,18.664)
  Bottom Layer w0.125: v1(14.325,11.25) 14.325,11.254 13.975,11.604 13.975,13.5 15.875,15.4 18.314,15.4 20.025,17.111 20.025,17.875 20.848,18.698 21.738,18.698 22.703,19.663 22.703,22.928 v1(23.275,23.5)
SWD0_RESET_EXT: P19.10 U7.10 | length 6
  Top Layer w0.125: 13.95,8.475 14.2,8.225 15.05,8.225 15.275,8 17.314,8 17.737,7.578 17.737,6.758 P19.10@18.044,6.45 ; 13.95,8.5 U7.10@13.95,9.085
SWD0_SEL: P19.3 Q1.5 U2.B24 | length 42.7
  Top Layer w0.125: v2(23.275,22.9) 23.554,22.9 23.804,23.15 23.804,24.15 ; v1(23.275,24.15) 23.804,24.15 ; Q1.5@27.263,24.047 27.263,24.433 27.101,24.596 25.987,24.596 25.542,24.15 23.804,24.15
  Top Layer w0.15: P19.3@14.234,2.55 v1(14.234,4.246)
  Mid-Layer 1 w0.125: v2(23.275,22.9) 22.941,22.566 22.941,19.943 23.835,19.049 23.835,18.689 v2(23.86,18.664)
  Bottom Layer w0.125: v1(14.234,4.246) 13.763,3.775 12.725,3.775 12.475,4.025 12.475,8.65 11.6,9.525 11.6,13.113 15.303,16.816 15.722,16.816 16.621,17.715 16.621,18.176 17.175,18.73 17.175,19.24 18.455,20.519 18.455,21.496 19.743,22.784 19.743,23.949 20.419,24.625 22.882,24.625 23.275,24.232 v1(23.275,24.15)
SWD0_SWO: U2.B20 U7.3 | length 24.1
  Top Layer w0.125: U7.3@13.55,10.365 13.55,11.024 13.675,11.149 v1(13.675,11.25)
  Mid-Layer 1 w0.125: v1(22.608,23.5) 22.536,23.428 22.536,23.236 22.391,23.091 22.391,19.655 23.06,18.986 v2(23.06,18.664)
  Bottom Layer w0.125: v1(13.675,11.25) 13.625,11.3 13.625,13.539 15.761,15.675 18.2,15.675 19.75,17.225 19.75,17.989 20.735,18.973 21.624,18.973 22.428,19.777 22.428,23.105 22.536,23.214 22.536,23.428 v1(22.608,23.5)
SWD0_SWO_EXT: P19.6 U7.9 | length 3.9
  Top Layer w0.125: U7.9@13.55,9.085 13.55,8.425 14.05,7.925 14.849,7.925 15.2,7.574 15.2,6.754 P19.6@15.504,6.45
SWD3_CLK: U2.R1 U14.3 | length 27.9
  Top Layer w0.125: U2.R1@19.06,16.064 18.715,16.064 18.124,16.655 17.105,16.655 16.825,16.375 16.825,15.065 16.567,14.807 16.567,12.183 20.514,8.236 v2(30.26,8.236) ; v2(30.894,12.65) U14.3@31.86,12.65
  Mid-Layer 1 w0.125: v2(30.26,8.236) 30.26,12.016 v2(30.894,12.65)
SWD3_CTRL: R31.2 U2.AB2 U6.1 U6.4 U6.11 | length 35.5
  Top Layer w0.125: v2(17.02,13.84) 16.831,13.651 16.831,12.315 20.53,8.617 v1(37.395,8.617)
  Top Layer w0.127: R31.2@35.191,13.25 U6.1@36.325,13.25 36.875,13.25 37.05,13.075 v2(37.05,12.85) ; U6.4@36.275,12.05 36.85,12.05 37.05,12.25 v2(37.05,12.85) ; U6.11@37.825,12.85 v2(37.05,12.85)
  Mid-Layer 1 w0.127: v2(17.02,13.84) 17.366,13.493 18.289,13.493 v4(19.46,14.664) ; v2(37.05,12.85) 37.395,12.505 v1(37.395,8.617)
SWD3_IO: U2.N1 U14.4 | length 28.9
  Top Layer w0.125: U2.N1@19.06,16.464 18.711,16.464 18.237,16.937 16.961,16.937 16.537,16.513 16.537,15.213 16.288,14.965 16.288,12.062 20.495,7.855 v2(30.666,7.855)
  Top Layer w0.127: v2(31.1,12.25) U14.4@31.86,12.25
  Mid-Layer 1 w0.127: v2(30.666,7.855) 30.666,11.816 v2(31.1,12.25)
SWD3_RESET: U2.AA1 U14.5 | length 28.5
  Top Layer w0.125: v2(16.145,15.352) 16.145,15.337 15.983,15.175 15.983,11.967 20.476,7.474 v2(31.047,7.474)
  Top Layer w0.127: v2(31.3,11.85) U14.5@31.86,11.85
  Mid-Layer 1 w0.125: v2(16.145,15.352) 16.948,15.352 17.436,14.864 v2(19.06,14.864)
  Mid-Layer 1 w0.127: v2(31.047,7.474) 31.047,11.597 v2(31.3,11.85)
TWI0_SCL: U2.AF2 U10.14 | length 55.6
  Top Layer w0.15: U10.14@19.692,48.296 19.699,48.303 v1@19.699,49.949
  Mid-Layer 1 w0.125: v1@17.975,12.376 v4@19.454,13.855
  Bottom Layer w0.125: v1(17.975,12.375) 18.025,12.375 18.475,12.825 18.475,14.725 19.775,16.025 20.625,16.025 21.225,16.625 21.225,17.812 21.548,18.135 21.993,18.135 23.288,19.431 23.288,22.461 23.564,22.737 24.799,22.737 26.366,24.304 26.366,45.137 28.1,46.871 28.1,48.903 26.765,50.237 23.112,50.237 22.175,49.3 21.025,49.3 20.375,49.95 v1(19.7,49.95)
  other v4: 19.46,13.864
TWI0_SDA: U2.AE1 U10.13 | length 52.1
  Top Layer w0.125: v1(17.269,14.385) 17.748,13.906 18.603,13.906 18.761,14.064 U2.AE1@19.059,14.064
  Top Layer w0.15: U10.13@20.192,48.296 v1@20.192,49.478
  Bottom Layer w0.125: v1(17.269,14.385) 18,15.116 18.458,15.116 20.442,17.1 20.675,17.1 20.952,17.377 20.952,17.916 21.46,18.423 21.873,18.423 23,19.55 23,22.58 23.445,23.025 24.679,23.025 26.077,24.423 26.077,45.257 27.811,46.991 27.811,48.783 26.645,49.95 23.233,49.95 22.295,49.012 20.905,49.012 20.493,49.424 20.226,49.424 v1(20.175,49.475)
UART0_CTRL: R14.2 U2.R31 U4.1 U4.4 U12.12 | length 52.6
  Top Layer w0.125: U2.R31@25.46,16.064 25.664,16.064 26.504,15.225 27.645,15.225 v2(27.926,15.506) ; v2(30.375,23.552) 32.5,23.552 ; U12.12@32.5,22 32.5,23.552 ; R14.2@32.61,25.214 v1(33.728,25.214) ; U4.4@47.003,43.837 47.345,43.837 47.5,43.992 47.5,44.804 47.267,45.037 U4.1@47.053,45.037 45.952,45.037 45.704,44.79 40.243,44.79 37.003,41.551 37.003,33.196 35.16,31.353 35.16,24.39 34.322,23.552 32.5,23.552
  Mid-Layer 1 w0.125: v2(27.926,15.506) 28.485,16.065 28.485,16.883 29.374,17.772 29.374,20.796 30.375,21.798 v2(30.375,23.552)
  Bottom Layer w0.125: v1(33.728,25.214) v1(35.16,25.214)
UART0_CTS: R32.1 U2.AL9 U12.5 | length 20.6
  Top Layer w0.125: v1(20.279,11.34) 20.279,11.372 20.742,11.834 20.742,11.836 20.86,11.954 U2.AL9@20.86,12.664
  Top Layer w0.127: v2(30.985,20.35) U12.5@31.86,20.35
  Mid-Layer 1 w0.125: v1@29.602,14.7 29.602,16.42 30.491,17.309 30.491,18.699 30.985,19.193 v2(30.985,20.35)
  Bottom Layer w0.125: v1(20.279,11.34) 20.775,11.836 20.775,12.167 21.233,12.625 ; 21.233,12.625 25.955,12.625 26.425,13.096 26.425,13.928 26.848,14.35 28.025,14.35 28.475,13.9 29.15,13.9 29.6,14.35 v1(29.6,14.7)
UART0_HWFC: R13.2 U2.AK16 U4.11 U4.15 | length 62
  Top Layer w0.125: v2(26.375,11.6) 27.182,11.6 30.827,15.245 v1(31.823,15.245) ; R13.2@32.61,24.575 32.825,24.575 32.964,24.436 v1(32.964,24) 34.084,24 34.703,24.619 34.703,31.603 36.503,33.403 36.503,41.758 40.035,45.29 45.504,45.29 45.782,45.568 v2(46.728,45.568) ; U4.15@47.578,45.612 47.622,45.568 47.622,45.147 47.734,45.036 47.946,45.036 v2(47.953,45.028) 47.987,44.994 47.987,44.863 48.168,44.682 48.508,44.682 U4.11@48.553,44.637
  Mid-Layer 1 w0.125: v2@22.27,13.074 v2(22.26,13.064) 22.26,12.89 21.092,11.722 21.092,11.128 22.232,9.989 25.686,9.989 26.375,10.678 v2(26.375,11.6) ; v2(46.728,45.568) 47.413,45.568 v2(47.953,45.028)
  Bottom Layer w0.125: v1(31.823,15.245) 31.823,18.013 31.493,18.343 31.493,23.263 31.783,23.552 32.516,23.552 v1(32.964,24)
UART0_RTS: U2.AL5 U12.4 | length 20.7
  Top Layer w0.125: v1(19.34,11.366) 19.797,11.823 19.797,12.23 20.059,12.492 U2.AL5@20.06,12.664 U2.AL5@20.06,12.664
  Top Layer w0.127: v2(30.35,20.833) 30.433,20.75 U12.4@31.86,20.75
  Mid-Layer 1 w0.125: v1(28.675,15.05) 28.675,15.443 29.043,15.811 29.043,16.652 29.932,17.541 29.932,18.93 30.35,19.348 v2(30.35,20.833)
  Bottom Layer w0.125: v1(19.34,11.366) 19.797,11.823 19.797,12.246 20.477,12.926 24.676,12.926 26.375,14.625 27.898,14.625 28.315,15.042 v1@28.667,15.042
UART0_RxD: U2.AL19 U12.3 | length 18.4
  Top Layer w0.125: U2.AL19@22.86,12.664 22.879,12.645 22.879,12.365 23.353,11.891 23.353,11.165 v4(23.237,11.05) ; v2(26.025,11.925) 27.101,11.925 29.14,13.965 v2(29.14,15.43)
  Top Layer w0.127: v2(31.1,21.15) U12.3@31.86,21.15
  Mid-Layer 1 w0.125: v4(23.237,11.05) 23.353,11.165 23.353,11.727 23.883,12.257 25.693,12.257 v2(26.025,11.925) ; v2(29.14,15.43) 29.323,15.612 29.323,16.536 30.212,17.425 30.212,18.815 30.629,19.232 30.629,20.526 31.1,20.997 v2(31.1,21.15) v2@31.067,21.117
UART0_TxD: U2.U31 U12.2 | length 11.8
  Top Layer w0.125: U2.U31@25.46,15.664 25.664,15.664 26.429,14.9 27.802,14.9 v2(27.926,15.023) ; v2(30.894,21.55) U12.2@31.86,21.55
  Mid-Layer 1 w0.125: v2(27.926,15.023) 27.926,15.062 28.764,15.9 28.764,16.768 29.653,17.657 29.653,20.644 30.559,21.55 v2(30.894,21.55)
UART1_CTRL: R16.2 U2.AK18 U5.1 U5.4 U13.12 | length 64.1
  Top Layer w0.125: v4(22.028,10.809) 22.028,10.319 23.349,8.998 26.924,8.998 28.989,11.063 31.127,11.063 32.607,9.582 v1(36.354,9.582) ; v2(32.5,17.154) U13.12@32.5,17.75 ; R16.2@32.61,27.098 v1@33.255,27.098 ; v1(37.751,16.796) 39.732,18.777 39.732,29.124 41.033,30.425 46.275,30.425 46.773,30.923 46.773,31.089 46.82,31.136 U5.4@46.947,31.136 ; U5.4@46.985,31.136 47.033,31.184 47.33,31.184 47.475,31.329 47.475,32.182 47.369,32.289 47.083,32.289 U5.1@47.035,32.336
  Top Layer w0.127: U5.4@46.947,31.136 U5.4@46.985,31.136
  Mid-Layer 1 w0.125: v4(22.028,10.809) 22.028,12.202 22.66,12.834 v2(22.66,13.064) ; v2(32.5,17.154) 32.646,17.3 37.247,17.3 v1(37.751,16.796)
  Bottom Layer w0.125: v1(33.267,27.111) 35.218,27.111 36.471,28.363 v1(39.732,28.363) ; v1(36.354,9.582) 36.354,14.053 37.751,15.45 v1(37.751,16.796)
UART1_CTS: R56.1 U2.AL15 U13.5 | length 15.5
  Top Layer w0.125: U2.AL15@22.06,12.664 22.06,12.226 22.336,11.95 22.336,11.389 23.889,9.836 26.598,9.836 29.043,12.282 v2(29.471,12.282) ; v2(30.985,16.09) 30.99,16.095 31.855,16.095 U13.5@31.86,16.1
  Mid-Layer 1 w0.125: v2(29.471,12.282) 30.737,13.548 30.737,15.377 30.985,15.624 v2(30.985,16.09)
UART1_HWFC: R15.2 U2.AK20 U5.11 U5.15 | length 58
  Top Layer w0.125: v4(22.4,10.446) 23.568,9.277 26.814,9.277 28.875,11.338 31.246,11.338 32.544,10.039 v1(35.49,10.039) ; R15.2@32.61,26.47 v1(33.728,26.47) ; v1(37.116,16.79) 39.275,18.949 39.275,29.339 40.836,30.9 v2(45.475,30.9) ; U5.15@47.56,32.911 47.605,32.867 47.605,32.446 47.744,32.307 47.935,32.307 v2(47.953,32.289) 47.987,32.255 47.987,32.199 48.202,31.984 48.488,31.984 U5.11@48.535,31.936
  Mid-Layer 1 w0.125: v4(22.4,10.446) 22.4,12.162 23.06,12.822 v2(23.06,13.064) ; v2(45.475,30.9) 45.475,31.646 46.117,32.289 v2(47.953,32.289)
  Bottom Layer w0.125: v1(33.728,26.47) 35.06,26.47 36.547,27.957 v1(39.275,27.957) ; v1(35.49,10.039) 36.075,10.624 36.075,14.205 37.116,15.246 v1(37.116,16.79)
UART1_RTS: U2.AL13 U13.4 | length 16.8
  Top Layer w0.125: U2.AL13@21.66,12.664 21.66,12.195 22.061,11.793 22.061,11.275 23.779,9.557 26.714,9.557 28.956,11.799 v2(29.471,11.799)
  Top Layer w0.127: v2(31.3,16.5) U13.4@31.86,16.5
  Mid-Layer 1 w0.125: v2(29.471,11.799) 31.078,13.406 31.078,15.235 31.456,15.613 31.456,16.339 31.3,16.496 v2(31.3,16.5)
UART1_RxD: U2.AL21 U13.3 | length 14.9
  Top Layer w0.125: U2.AL21@23.26,12.664 23.26,12.431 23.658,12.033 23.658,10.575 24.117,10.116 26.482,10.116 29.131,12.764 v2(29.471,12.764)
  Top Layer w0.127: v2(31.1,16.9) U13.3@31.86,16.9
  Mid-Layer 1 w0.125: v2(29.471,12.764) 30.396,13.689 30.396,15.518 30.651,15.773 30.651,16.451 v2(31.1,16.9)
UART1_TxD: U2.AL23 U13.2 | length 14.5
  Top Layer w0.125: U2.AL23@23.66,12.664 23.671,12.654 23.671,12.457 23.962,12.165 23.962,10.697 24.265,10.395 26.366,10.395 29.218,13.247 v2(29.471,13.247) ; v2(30.894,17.3) U13.2@31.86,17.3
  Mid-Layer 1 w0.125: v2(29.471,13.247) 30.055,13.831 30.055,15.659 30.31,15.915 30.31,16.717 v2(30.894,17.3)
VBUS: C23.2 C54.1 J4.5 R5.2 R36.2 SW4.4 TP8.1 U10.21 | length 132.2
  Top Layer w0.125: v1(6.075,51.975) R36.2@6.075,52.515 ; R5.2@28.56,9.937 28.56,10.29 28.786,10.516 29.216,10.516 v1(29.275,10.575)
  Top Layer w0.3: C23.2@15.684,45.313 15.702,45.295 16.78,45.295 17.081,45.596 U10.21@17.992,45.596
  Top Layer w0.5: C23.2@15.684,45.313 15.684,44.191 C54.1@15.775,44.1
  Top Layer w0.75: 15.775,43.525 C54.1@15.775,44.1
  Top Layer w0.8: SW4.4@5.721,60.488 7.337,60.488 8.6,59.225 v1(8.6,51.969) 8.6,46.471 11.946,43.125 v1(12.775,43.125) 15.375,43.125 15.775,43.525
  Bottom Layer w0.125: v1(6.075,51.975) 8.594,51.975 v1(8.6,51.969) ; v1(26.958,2.074) 27.593,2.709 30.808,2.709 31.328,3.23 31.328,6.597 29.275,8.65 v1(29.275,10.575)
  Bottom Layer w0.25: v1(12.775,43.125) 10.25,43.125 4.775,37.65 4.775,13.2 11.184,6.791 11.184,3.391 13.2,1.375 26.3,1.375 26.958,2.033 v1(26.958,2.074)
  Bottom Layer w0.5: v1(8.6,51.969) 15.024,51.969 16.482,53.427 16.482,58.532 17.625,59.675 21.736,59.675 TP8.1@23.372,58.039
VBUS:IN1: C30.1 C47.2 C48.2 D1.5 FB4.1 J3.A4 J3.A9 TP16.1 | length 10.9
  Top Layer w0.2: v1(8.527,24.134) D1.5@9.135,24.134
  Top Layer w0.45: J3.A9@7.485,21.734 7.487,21.732 v1(8.517,21.732)
  Bottom Layer w0.2: v1@8.519,21.73 v1(8.517,21.732) 8.137,21.732 7.943,21.927 7.943,22.892 8.527,23.477 v1(8.527,24.134)
  Bottom Layer w0.45: v1@8.519,21.73 12.548,21.73 13.263,22.446 TP16.1@13.263,23.571
VBUS:IN2: C46.2 FB4.2 SW4.5 | length 33.3
  Top Layer w0.5: FB4.2@11.475,27.8 11.475,28.423
  Top Layer w0.8: SW4.5@5.721,57.988 7.031,57.988 7.6,57.42 7.6,46.05 11.475,42.175 11.475,28.423
VBUSOUT: C68.2 U10.22 | length 4.1
  Top Layer w0.2: C68.2@15.702,42.275 16.525,43.098 16.525,44.202 17.408,45.086 17.981,45.086 U10.22@17.992,45.096
VDD: C25.2 C58.1 FB3.2 P6.3 R24.2 TP9.1 | length 22.4
  Top Layer w0.3: v1(25.832,58.5) v1(25.832,59.141)
  Top Layer w0.5: v1(25.832,59.141) P6.3@25.832,62.071
  Top Layer w0.75: v1(25.832,58.5) 25.887,58.5 25.967,58.421 25.967,57.464 26.406,57.025 28.436,57.025 28.875,56.586 C58.1@28.875,49.139 ; FB3.2@28.887,47.665 28.887,48.321 C58.1@28.887,49.139
  Bottom Layer w0.2: v1(25.832,58.5) 25.832,55.901 26.818,54.915 TP9.1@26.877,54.915
  Bottom Layer w0.55: v1@25.826,59.141 v1(25.832,59.141) ; v1(25.832,58.5) v1(25.832,59.141) ; R24.2@26.599,59.141 v1(25.832,59.141)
